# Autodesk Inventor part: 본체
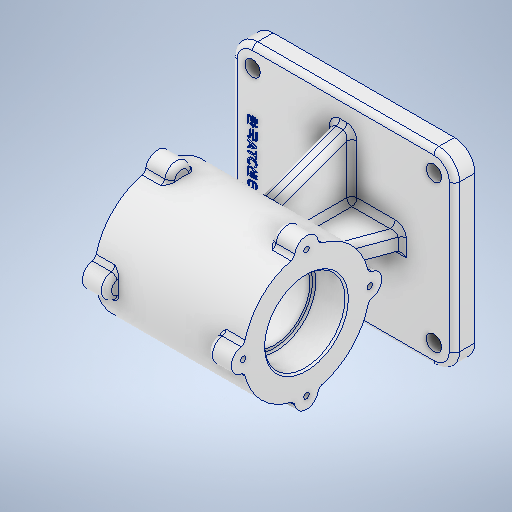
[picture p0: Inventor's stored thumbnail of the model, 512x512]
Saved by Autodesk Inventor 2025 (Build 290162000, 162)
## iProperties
Created: 2025-08
Part Number: 본체
Material: 알루미늄 6061
Document SubType Name: Modeling
Designer: infra02
Density: 2.7 g/cm^3
Appearance: 알루미늄 - 평지
Mass: 1221.43 g
Surface Area: 808.887 cm^2
Volume: 452.382 cm^3
Author: infra02
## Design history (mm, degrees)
sketch "스케치1"
  geometry: L1 (65, -55)-(-65, -55); L2 (-65, -55)-(-65, 55); L3 (-65, 55)-(65, 55); L4 (65, 55)-(65, -55); L5 (65, -55)-(-65, 55); L6 (-65, -55)-(65, 55); 1 further point
  constraints: 12 end point, 2 midpoint, 2 parallel, 1 horizontal, 1 perpendicular
  dimensions: "d0" = 130 distance of L2.end L3.end; "d1" = 110 distance of L1.end L2.end
extrude "돌출1" new body sketch "스케치1" distance "d2" = 12; taper "d3" = 0 deg
sketch "스케치3"
  geometry: L1 (38.5, 119)-(-48.5, 119); L2 (-48.5, 119)-(-48.5, 82); L3 (-48.5, 82)-(38.5, 82); L4 (38.5, 82)-(38.5, 119); L5 (38.5, 105.5)-(19.5, 105.5); L6 (19.5, 105.5)-(19.5, 82); L7 (19.5, 82)-(38.5, 82); L8 (38.5, 82)-(38.5, 105.5); L9 (19.5, 103)-(-29.5, 103); L10 (-29.5, 103)-(-29.5, 82); L11 (-29.5, 82)-(19.5, 82); L12 (19.5, 82)-(19.5, 103); L13 (-29.5, 103)-(-29.5, 105.5); L14 (-29.5, 105.5)-(-48.5, 105.5); L15 (65, 0)-(65, 12) reference; L16 (65, 0)-(-65, 0) reference; 2 further points
  constraints: 28 end point, 6 parallel, 5 point on line, 4 perpendicular, 3 horizontal, 1 midpoint, 1 vertical
  dimensions: "d6" = 19 distance between parallel lines of L6 L4; "d7" = 19 distance between parallel lines of L2 L10; "d8" = 87 distance between parallel lines of L2 L4; "d9" = 23.5 distance between parallel lines of L5 L3; "d10" = 21 distance between parallel lines of L9 L11; "d11" = 23.5 distance between parallel lines of L14 L3 (= d9); "d12" = 70 distance from line of point (-5, 82) L15; "d13" = 82 distance between parallel lines of L11 L16; "d14" = 37 distance between parallel lines of L1 L11
revolve "회전1" sketch "스케치3" stored, may be unused: angle "d15" = 90 deg
sketch "스케치4"
  geometry: L1 (0, 0)-(37, 0); C1 r 7 at (37, 0); C2 r 7 at (0, 37); C3 r 7 at (-37, 0); C4 r 7 at (0, -37); A1 r 37 centre (0, 0) between (37, 0) and (0, 37) reference; 1 further point
  constraints: 4 centre point, 2 end point, 2 point on circle, 2 vertical alignment, 1 coincident, 1 horizontal, 9 other
  dimensions: "d16" = 14 diameter of C1; "d19" = 360 deg dimension on L1.start C1.centre (derived); "d21" = 0 distance from line of A1.centre L1
  node "스케치 - 원형 패턴1" dims "d19" = 360 deg (derived)
extrude "돌출2" join sketch "스케치4" distance "d22" = 14; taper "d23" = 0 deg
hole "구멍1" sketch "스케치4" diameter "d24" = 3.242; stored, may be unused: countersink angle "d28" = 90 deg, drill point angle "d30" = 118 deg; dims "d25" = 8, "d26" = 4, "d27" = 2, "d29" = 10
node "작업 평면1"
sketch "스케치6"
  geometry: C1 r 7 at (-37, 37) reference; C2 r 7 at (-74, 0) reference; C3 r 7 at (0, 0) reference; C4 r 1.621 at (-37, -37) reference; C5 r 1.621 at (0, 0) reference; C6 r 1.621 at (-37, 37) reference; C7 r 1.621 at (-74, 0) reference; A1 r 7 centre (-37, -37) between (-43.969, -36.338) and (-30.031, -36.338) reference; A2 r 7 centre (-37, -37) between (-43.969, -36.338) and (-30.031, -36.338) reference; 1 further point
extrude "돌출3" join sketch "스케치6" distance "d32" = 14; taper "d33" = 0 deg
hole "구멍2" sketch "스케치6" diameter "d34" = 3.242; stored, may be unused: countersink angle "d38" = 90 deg, drill point angle "d40" = 118 deg; dims "d35" = 8, "d36" = 4, "d37" = 2, "d39" = 10
sketch "스케치9"
  geometry: L1 (-34.5, 45)-(24.5, 45) reference; L2 (13.263, 45)-(25.274, 12); L3 (65, 12)-(-65, 12) reference; L4 (-22.032, 46.877)-(-34.726, 12); 3 further points
  constraints: 4 end point, 2 point on line
  dimensions: "d43" = 110 deg angle of L2 L3; "d44" = 110 deg angle of L3 L4; "d45" = 60 distance of L4.end L2.end
extrude "돌출4" join sketch "스케치9" stored distance "d46" = 10; taper "d47" = 0 deg
sketch "스케치10"
  geometry: L1 (25.336, 55.036)-(41, 12); L2 (55, 12)-(-55, 12) reference; L3 (-25.336, 55.036)-(-41, 12); A1 r 37 centre (0, 82) between (6.969, 45.662) and (36.338, 75.031) reference; A2 r 37 centre (0, 82) between (-36.338, 75.031) and (-6.969, 45.662) reference; 1 further point
  constraints: 4 end point, 2 point on circle, 2 point on line
  dimensions: "d48" = 110 deg angle of L1 L2; "d49" = 110 deg angle of L2 L3; "d50" = 14 distance of L1.end L2.start; "d51" = 14 distance of L2.end L3.end
feature "리브1" dims "d52" = 1, "d53" = 10, "d54" = 0, "d55" = 0, "d56" = 1, "d57" = 1
feature "리브2" dims "d58" = 1, "d59" = 10, "d60" = 0, "d61" = 0, "d62" = 1, "d63" = 1
sketch "스케치11"
  geometry: L1 (53, 43)-(-53, 43); L2 (-53, 43)-(-53, -43); L3 (-53, -43)-(53, -43); L4 (53, -43)-(53, 43); L5 (-65, 55)-(-65, -55) reference; L6 (-65, -55)-(65, -55) reference; L7 (65, 55)-(-65, 55) reference; 5 further points
  constraints: 8 end point, 4 coincident, 2 parallel, 1 horizontal, 1 perpendicular
  dimensions: "d64" = 12 distance between parallel lines of L2 L5; "d65" = 106 distance of L2.end L3.end; "d66" = 86 distance of L3.end L1.start; "d67" = 12 distance between parallel lines of L6 L3; "d68" = 110 distance between parallel lines of L6 L7 (derived)
hole "구멍3" sketch "스케치11" at (53, 43), (53, -43), (-53, 43), (-53, -43) diameter "d69" = 9; stored, may be unused: countersink angle "d73" = 90 deg, drill point angle "d75" = 118 deg; dims "d70" = 8, "d71" = 4, "d72" = 2, "d74" = 10
fillet "모깎기1" dims "d76" = 12
chamfer "모따기1" distance "d77" = 1; stored, may be unused: second distance "d78" = 2, angle "d79" = 45 deg
chamfer "모따기2" distance "d80" = 1; stored, may be unused: second distance "d81" = 2, angle "d82" = 45 deg
fillet "모깎기2" dims "d83" = 1
fillet "모깎기3" dims "d84" = 3
fillet "모깎기4" dims "d85" = 3
fillet "모깎기5" dims "d86" = 3
fillet "모깎기6" dims "d87" = 3
node "작업 평면2"
sketch "스케치14"
  geometry: L1 (-55.829, 19.887)-(-55.829, -19.887); L2 (-55.829, -19.887)-(-50.171, -19.887); L3 (-50.171, -19.887)-(-50.171, 19.887); L4 (-50.171, 19.887)-(-55.829, 19.887); L5 (-65, 43)-(-65, -43) reference; L6 (5, 66.257)-(5, -70.664); 5 further points
  constraints: 3 midpoint, 2 end point, 1 horizontal alignment, 1 vertical, 1 vertical alignment, 2 other
  dimensions: "d89" = 70 distance between parallel lines of L6 L5; "d90" = 58 distance from line of L6 point (-53, 19.887) (derived)
feature "엠보싱1" sketch "스케치14" dims "d0" = 130, "d1" = 110, "d10" = 21, "d91" = 0.5, "d92" = 0
node "솔리드1"
feature "A9D066F2-1C7D-4E18-AEED-F7BC21143FA4" dims "d69" = 9, "d70" = 8, "d71" = 4, "d72" = 2, "d73" = 90 deg, "d74" = 10, "d75" = 118 deg
other parameters: "d31" = -87, "d88" = 0
